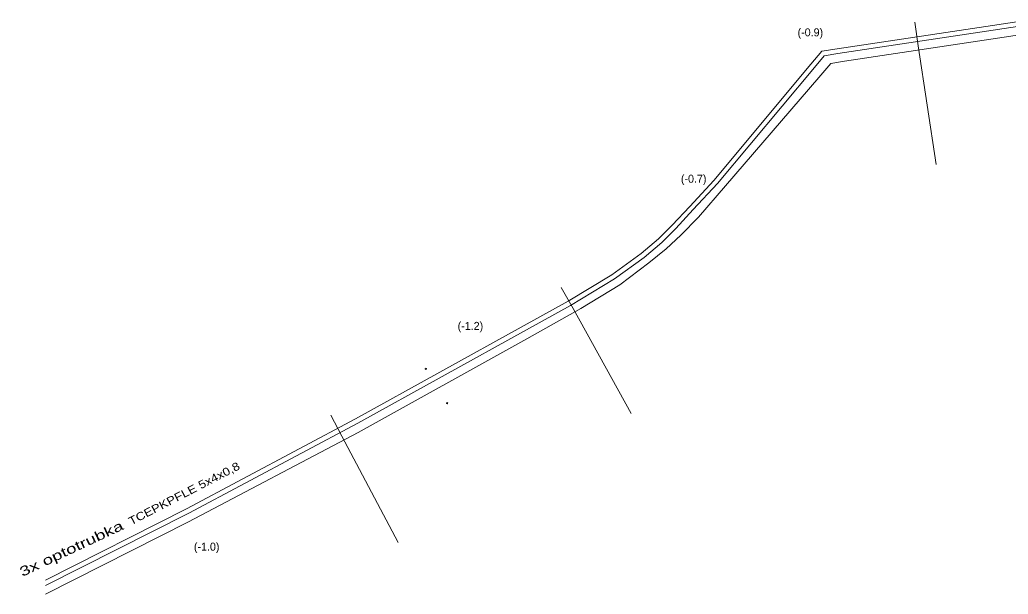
# Model space of a CAD drawing. Extents: x -725606 to -725269, y -977352 to -977136.
# Drawn here: x -725605.8 to -725544.1, y -977268.2 to -977232.3 of the extents above; entities that cross this region are included whole.
import ezdxf
from ezdxf.enums import TextEntityAlignment as Align

# ---------------------------------------------------------------- set-up
doc = ezdxf.new("R2010")
doc.units = 0
doc.header["$LTSCALE"] = 0.2
for name, color, linetype, lineweight in [('43', 7, 'Continuous', 13), ('47', 7, 'Continuous', 13), ('48', 7, 'Continuous', 13), ('63', 7, 'Continuous', 13)]:
    doc.layers.add(name, color=color, linetype=linetype, lineweight=lineweight)
doc.layers.add('46', color=7, linetype='Continuous')
doc.layers.add('7', color=7, linetype='Continuous')

msp = doc.modelspace()

# ---------------------------------------------------------------- linework, layer by layer
at = {"layer": '43'}
msp.add_lwpolyline([(-725572, -977248.99), (-725571.27, -977250.3), (-725567.63, -977256.86)], dxfattribs=at)
for points in [[(-725580.461, -977254.124), (-725580.499, -977254.102), (-725580.498, -977254.058), (-725580.459, -977254.036), (-725580.421, -977254.058), (-725580.422, -977254.102)], [(-725579.138, -977256.176), (-725579.101, -977256.198), (-725579.102, -977256.242), (-725579.142, -977256.264), (-725579.179, -977256.242), (-725579.178, -977256.198)]]:
    msp.add_lwpolyline(points, close=True, dxfattribs=at)
at = {"layer": '47'}
msp.add_lwpolyline([(-725586.41, -977256.96), (-725585.71, -977258.29), (-725582.2, -977264.92)], dxfattribs=at)
at = {"layer": '48'}
msp.add_lwpolyline([(-725549.92, -977232.4), (-725549.7, -977233.88), (-725548.58, -977241.3)], dxfattribs=at)
at = {"layer": '63'}
for points in [[(-725542.704, -977232.253), (-725554.765, -977234.073), (-725555.727, -977234.221), (-725556.41, -977235.038), (-725562.475, -977242.292), (-725563.98, -977243.916), (-725565.066, -977245.092), (-725565.923, -977245.949), (-725567.015, -977246.874), (-725568.836, -977248.19), (-725571.57, -977249.85), (-725574.325, -977251.367), (-725584.863, -977257.206), (-725595.418, -977262.824), (-725604.24, -977267.284)], [(-725542.66, -977232.55), (-725554.72, -977234.37), (-725555.57, -977234.5), (-725556.18, -977235.23), (-725562.25, -977242.49), (-725563.76, -977244.12), (-725564.85, -977245.3), (-725565.72, -977246.17), (-725566.83, -977247.11), (-725568.67, -977248.44), (-725571.42, -977250.11), (-725574.18, -977251.63), (-725584.72, -977257.47), (-725595.28, -977263.09), (-725604.24, -977267.621)], [(-725604.24, -977268.164), (-725595.29, -977263.63), (-725584.7, -977258.05), (-725574.15, -977252.19), (-725570.79, -977250.31), (-725568.35, -977248.82), (-725566.53, -977247.45), (-725565.45, -977246.57), (-725564.53, -977245.72), (-725563.42, -977244.6), (-725561.75, -977242.63), (-725555.91, -977235.86), (-725555.15, -977234.98), (-725554.3, -977234.85), (-725542.4, -977233.05)]]:
    msp.add_lwpolyline(points, dxfattribs=at)

# ---------------------------------------------------------------- texts
at = {"layer": '46'}
for s, p in [('(-0.9)', (-725556.44, -977233.29)), ('(-0.7)', (-725563.73, -977242.44)), ('(-1.2)', (-725577.68, -977251.64)), ('(-1.0)', (-725594.16, -977265.44))]:
    msp.add_text(s, height=0.5, dxfattribs=at).set_placement(p, align=Align.CENTER)
at = {"layer": '63', "width": 1.2}
msp.add_text('TCEPKPFLE 5x4x0,8', height=0.5, rotation=27.387, dxfattribs=at).set_placement((-725595.4525, -977262.0887), align=Align.CENTER)
at = {"layer": '7', "width": 1.45}
msp.add_text('3x optotrubka', height=0.6, rotation=25.153, dxfattribs=at).set_placement((-725602.487, -977265.583), align=Align.CENTER)

doc.saveas('drawing.dxf')
